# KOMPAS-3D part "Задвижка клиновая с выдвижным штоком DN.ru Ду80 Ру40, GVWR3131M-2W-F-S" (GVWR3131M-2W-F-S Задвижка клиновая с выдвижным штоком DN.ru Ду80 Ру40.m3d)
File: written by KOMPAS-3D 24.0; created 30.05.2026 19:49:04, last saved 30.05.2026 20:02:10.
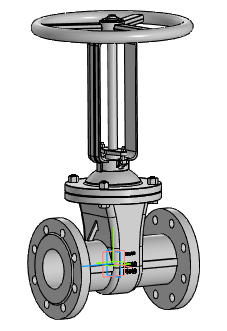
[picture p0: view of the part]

Document properties: Автор: R2D2; Полное имя файла: E:\Работа\Зайцев\GVWR3131M-2W-F-S Задвижка клиновая с выдвижным штоком DN.ru Ду50-100 Ру40\исходные материалы\DN80\GVWR3131M-2W-F-S Задвижка клиновая с выдвижным штоком DN.ru Ду80 Ру40.m3d

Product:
- Component [detail]: Деталь2  | qty 1  | pos. 1  | Автор: R2D2; additional columns: Типовые; source file: Деталь2 Деталь2.m3d
- Component [detail]: AS 1110 - M12 x 45  | qty 4  | pos. 2  | Комментарий: Болты и винты   шестигранные точные   метрические ISO; Автор: R2D2; additional columns: Сталь, мягкая; source file: AS 1110 - M12 x 45 AS 1110 - M12 x 45.m3d
- Component [detail]: ANSI B18.2.4.2M - M12x1,75 - 18  | designation ANSI B18.2.4.2M - M12x1,75  | qty 4  | pos. 3  | Комментарий: Типы метрических   шестигранных гаек   2; Автор: R2D2; additional columns: Сталь, мягкая; source file: ANSI B18.2.4.2M - M12x1,75 ANSI B18.2.4.2M - M12x1,75 - 18.m3d
- Component [detail]: ANSI B18.2.4.2M - M5x0,8 - 8  | designation ANSI B18.2.4.2M - M5x0,8  | qty 2  | pos. 4  | Комментарий: Типы метрических   шестигранных гаек   2; Автор: R2D2; additional columns: Сталь, мягкая; source file: ANSI B18.2.4.2M - M5x0,8 ANSI B18.2.4.2M - M5x0,8 - 8.m3d
- Component [detail]: Деталь1  | qty 1  | pos. 5  | additional columns: Типовые; source file: 2.m3d
- Component [detail]: Деталь1  | qty 1  | pos. 5  | Автор: R2D2; additional columns: Типовые; source file: 3.m3d
- Component [detail]: Деталь1  | qty 2  | pos. 5  | Автор: R2D2; additional columns: Типовые; source file: 1.m3d
- Part/product: Задвижка клиновая с выдвижным штоком DN.ru Ду80 Ру40  | designation GVWR3131M-2W-F-S
    Масса: 31
    Раздел спецификации: Прочие изделия
    Примечание: D040-07874

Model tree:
1. Массив по концентрической сетке:1  (labels: Грань.Твердое тело1)  (4 pattern instances)
     Шаг 2 = 360
2. Массив по концентрической сетке:2  (labels: Грань.Твердое тело1)  (2 pattern instances)
     Шаг 2 = 360
3. Элемент выдавливания:1  (with: Грань.Элемент выдавливания:2, Грань.Элемент вращения:1)
     Расстояние 1 = 40.7058
4. Элемент выдавливания:2  (with: Грань.Элемент выдавливания:1, Грань.Элемент вращения:1)
     Расстояние 1 = 35.7507
5. Элемент выдавливания:3  (with: Грань.Элемент выдавливания:1)
     Расстояние 1 = 125.25
6. Эскиз:1
7. Элемент выдавливания:4  (with: Грань.Элемент выдавливания:1, Грань.Элемент вращения:1)  (labels: Грань.Твердое тело1; Грань.Solid1; Твердое тело1)
     Расстояние 1 = 61; Смещение 1 = 1; Расстояние = -495; Расстояние = -140; Ориентация = 2

Referenced files in E:\Работа\Зайцев\GVWR3131M-2W-F-S Задвижка клиновая с выдвижным штоком DN.ru Ду50-100 Ру40\исходные материалы\DN80\: Деталь2 Деталь2.m3d, AS 1110 - M12 x 45 AS 1110 - M12 x 45.m3d, ANSI B18.2.4.2M - M12x1,75 ANSI B18.2.4.2M - M12x1,75 - 18.m3d, ANSI B18.2.4.2M - M5x0,8 ANSI B18.2.4.2M - M5x0,8 - 8.m3d, 2.m3d, 3.m3d, 1.m3d
Referenced files in E:\Работа\Зайцев\GVWR3131M-2W-F-S Задвижка клиновая с выдвижным штоком DN.ru Ду50-200 Ру63\DN80\исходные материалы\: 1.m3d, ANSI B18.2.4.2M - M12x1,75 ANSI B18.2.4.2M - M12x1,75 - 18.m3d, AS 1110 - M12 x 45 AS 1110 - M12 x 45.m3d, ANSI B18.2.4.2M - M5x0,8 ANSI B18.2.4.2M - M5x0,8 - 8.m3d
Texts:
  GVWR3131M-2W-F-S
  DN80
  GOST 26.020 Pr3
  PN40
  Деталь2 Деталь2
  AS 1110 - M12 x 45 AS 1110 - M12 x 45 (1)
  ANSI B18.2.4.2M - M12x1,75 ANSI B18.2.4.2M - M12x1,75 - 18 (1)
  ANSI B18.2.4.2M - M5x0,8 ANSI B18.2.4.2M - M5x0,8 - 8 (1)
  Деталь1 Деталь1
  Деталь1 Деталь1 (1)
  Деталь1 Деталь1 (2)
  Ось Y.Начало координат
  Ось Z.Начало координат
  Плоскость ZX.Начало координат
  Плоскость XY.Начало координат
  Solid1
